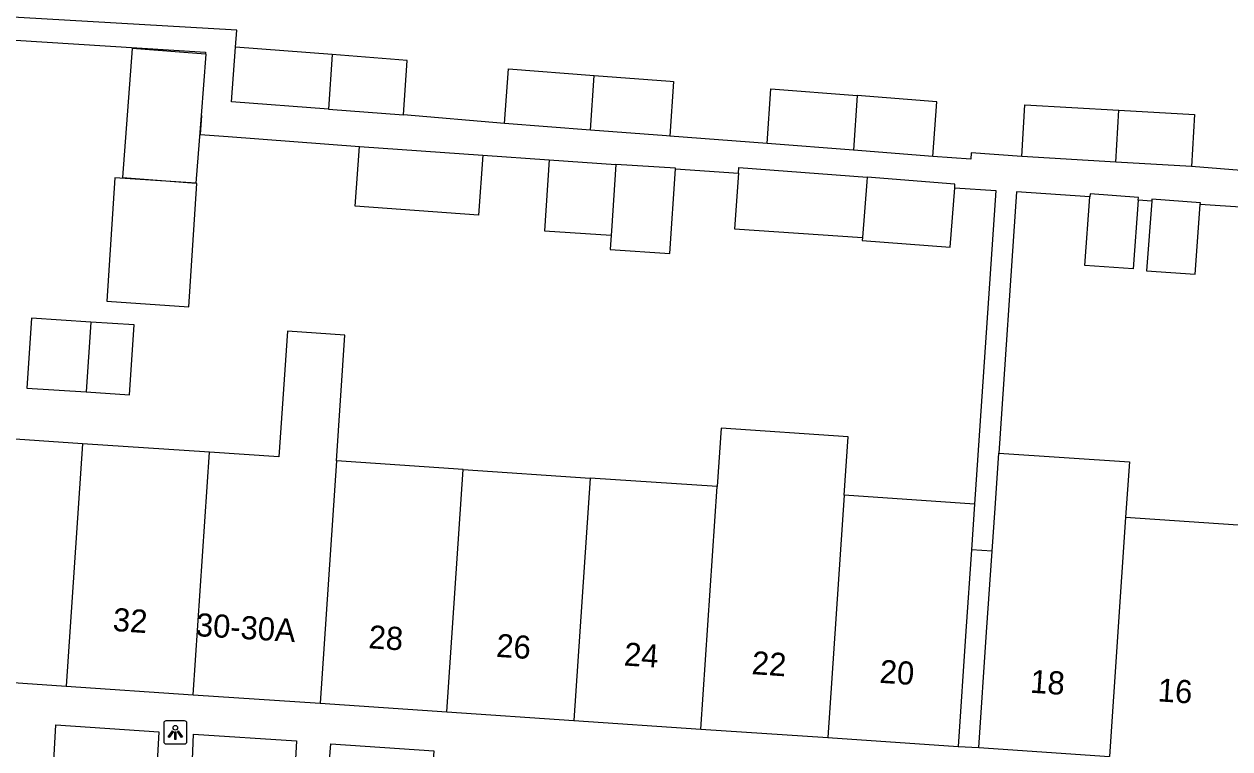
# Model space of a CAD drawing. Extents: x 159961 to 160856, y 382704 to 383353.
# Drawn here: x 160654.9 to 160707.1, y 382890.9 to 382922.3 of the extents above; entities that cross this region are included whole.
import ezdxf

# ---------------------------------------------------------------- set-up
doc = ezdxf.new("R2010")
doc.units = 0
for name, color, linetype in [('IMGEO_Lichtpunt', 7, 'Continuous'), ('IMGEO_Pand', 7, 'Continuous'), ('IMGEO_Pand_nummerreeks', 7, 'Continuous'), ('IMGEO_Pand_overbouw', 7, 'Continuous'), ('IMGEO_Voetpad_open', 7, 'Continuous')]:
    doc.layers.add(name, color=color, linetype=linetype)

msp = doc.modelspace()

# ---------------------------------------------------------------- linework, layer by layer
at = {"layer": 'IMGEO_Lichtpunt'}
for p, q in [((160660.981, 382892.057), (160660.981, 382891.25)), ((160660.981, 382892.057), (160660.981, 382891.25)), ((160661.883, 382892.152), (160661.075, 382892.152)), ((160661.883, 382892.152), (160661.075, 382892.152)), ((160661.977, 382891.25), (160661.977, 382892.057)), ((160661.977, 382891.25), (160661.977, 382892.057)), ((160661.075, 382891.156), (160661.883, 382891.156)), ((160661.075, 382891.156), (160661.883, 382891.156))]:
    msp.add_line(p, q, dxfattribs=at)
for points in [[(160661.355, 382891.721), (160661.394, 382891.693), (160661.206, 382891.431), (160661.168, 382891.458), (160661.355, 382891.721)], [(160661.457, 382891.673), (160661.504, 382891.673), (160661.504, 382891.351), (160661.457, 382891.351), (160661.457, 382891.673)], [(160661.567, 382891.693), (160661.605, 382891.72), (160661.792, 382891.458), (160661.753, 382891.43), (160661.567, 382891.693)]]:
    msp.add_lwpolyline(points, dxfattribs=at)
msp.add_circle((160661.48, 382891.855), 0.0994, dxfattribs=at)
for centre, start, end in [((160661.075, 382892.057), 90, 180), ((160661.075, 382892.057), 90, 180), ((160661.883, 382892.057), 0, 90), ((160661.883, 382892.057), 0, 90), ((160661.075, 382891.25), 180, 270), ((160661.075, 382891.25), 180, 270), ((160661.883, 382891.25), 270, 0), ((160661.883, 382891.25), 270, 360)]:
    msp.add_arc(centre, 0.0946, start, end, dxfattribs=at)
at = {"layer": 'IMGEO_Pand'}
for points in [[(160662.784, 382920.999), (160659.618, 382921.242), (160659.189, 382915.651), (160662.375, 382915.407)], [(160668.102, 382918.612), (160663.905, 382918.935), (160664.086, 382921.294)], [(160668.261, 382920.973), (160664.086, 382921.294)], [(160662.609, 382918.34), (160662.813, 382920.997), (160662.784, 382920.999)], [(160668.261, 382920.973), (160668.102, 382918.612)], [(160671.34, 382918.363), (160671.508, 382920.723), (160668.261, 382920.973)], [(160675.717, 382917.997), (160675.885, 382920.359), (160679.593, 382920.074)], [(160679.431, 382917.712), (160679.593, 382920.074)], [(160679.593, 382920.074), (160682.877, 382919.821), (160683.021, 382919.81), (160682.86, 382917.448)], [(160687.073, 382917.124), (160687.234, 382919.486), (160690.968, 382919.2)], [(160690.968, 382919.2), (160690.806, 382916.837)], [(160694.23, 382916.573), (160694.411, 382918.935), (160690.968, 382919.2)], [(160668.102, 382918.612), (160671.34, 382918.363)], [(160698.086, 382916.56), (160698.215, 382918.8), (160702.28, 382918.566)], [(160662.384, 382915.406), (160662.609, 382918.34)], [(160702.151, 382916.327), (160702.28, 382918.566)], [(160702.28, 382918.566), (160705.546, 382918.378), (160705.417, 382916.139)], [(160679.431, 382917.712), (160675.717, 382917.997)], [(160682.86, 382917.448), (160682.716, 382917.459), (160679.431, 382917.712)], [(160690.806, 382916.837), (160687.073, 382917.124)], [(160674.774, 382916.621), (160674.589, 382914.033), (160669.26, 382914.412), (160669.445, 382917)], [(160669.445, 382917), (160674.774, 382916.621)], [(160694.23, 382916.573), (160690.806, 382916.837)], [(160702.151, 382916.327), (160698.086, 382916.56)], [(160677.637, 382916.418), (160677.435, 382913.347), (160680.328, 382913.157)], [(160677.637, 382916.418), (160680.53, 382916.225)], [(160680.328, 382913.157), (160680.288, 382912.546), (160682.862, 382912.376), (160683.104, 382916.038)], [(160680.53, 382916.225), (160680.341, 382913.349), (160680.328, 382913.157)], [(160683.104, 382916.038), (160683.105, 382916.055), (160680.53, 382916.225)], [(160685.824, 382915.843), (160685.841, 382916.093), (160691.389, 382915.667)], [(160705.417, 382916.139), (160702.151, 382916.327)], [(160662.375, 382915.407), (160658.868, 382915.637), (160658.517, 382910.302), (160662.065, 382910.069), (160662.416, 382915.404), (160662.384, 382915.406)], [(160685.824, 382915.843), (160685.661, 382913.442), (160691.189, 382913.067)], [(160691.389, 382915.667), (160691.374, 382915.468), (160691.189, 382913.067)], [(160695.177, 382915.211), (160695.19, 382915.375), (160691.389, 382915.667)], [(160662.375, 382915.407), (160662.384, 382915.406)], [(160691.189, 382913.067), (160691.179, 382912.932), (160694.98, 382912.64), (160695.177, 382915.211)], [(160703.116, 382914.675), (160703.125, 382914.796), (160701.031, 382914.95), (160701.021, 382914.816)], [(160703.116, 382914.675), (160702.899, 382911.705), (160700.805, 382911.858), (160701.021, 382914.816)], [(160703.698, 382914.635), (160703.478, 382911.623), (160705.572, 382911.47), (160705.794, 382914.494)], [(160705.794, 382914.494), (160705.799, 382914.561), (160703.704, 382914.714), (160703.698, 382914.635)], [(160657.826, 382909.404), (160655.263, 382909.573), (160655.064, 382906.55), (160657.622, 382906.382)], [(160657.826, 382909.404), (160657.622, 382906.382)], [(160657.622, 382906.382), (160659.502, 382906.259), (160659.7, 382909.281), (160657.826, 382909.404)], [(160668.445, 382903.4), (160668.813, 382908.841), (160666.328, 382909.009), (160665.961, 382903.568), (160662.957, 382903.771)], [(160657.47, 382904.142), (160651.833, 382904.524), (160651.461, 382899.027), (160651.124, 382894.038)], [(160690.395, 382901.914), (160690.566, 382904.437), (160685.078, 382904.808), (160684.907, 382902.285)], [(160657.47, 382904.142), (160656.761, 382893.656)], [(160662.957, 382903.771), (160657.47, 382904.142)], [(160662.248, 382893.285), (160662.957, 382903.771)], [(160696.222, 382890.997), (160696.56, 382895.986), (160696.798, 382899.488), (160696.924, 382901.351), (160697.085, 382903.733)], [(160697.085, 382903.733), (160702.731, 382903.351), (160702.57, 382900.969)], [(160668.445, 382903.4), (160667.736, 382892.913)], [(160673.932, 382903.028), (160668.445, 382903.4)], [(160673.223, 382892.542), (160673.932, 382903.028)], [(160673.932, 382903.028), (160679.42, 382902.657)], [(160679.42, 382902.657), (160678.711, 382892.171)], [(160684.907, 382902.285), (160679.42, 382902.657)], [(160684.198, 382891.799), (160684.907, 382902.285)], [(160690.395, 382901.914), (160689.686, 382891.428)], [(160696.034, 382901.532), (160690.395, 382901.914)], [(160696.034, 382901.532), (160695.9, 382899.549), (160695.661, 382896.035), (160695.323, 382891.046)], [(160702.57, 382900.969), (160701.869, 382890.615)], [(160702.57, 382900.969), (160708.069, 382900.596)], [(160651.124, 382894.038), (160656.761, 382893.656)], [(160656.761, 382893.656), (160662.248, 382893.285)], [(160662.248, 382893.285), (160667.736, 382892.913)], [(160667.736, 382892.913), (160673.223, 382892.542)], [(160673.223, 382892.542), (160678.711, 382892.171)], [(160678.711, 382892.171), (160684.198, 382891.799)], [(160684.198, 382891.799), (160689.686, 382891.428)], [(160689.686, 382891.428), (160695.323, 382891.046)], [(160696.222, 382890.997), (160701.869, 382890.615)]]:
    msp.add_lwpolyline(points, dxfattribs=at)
at = {"layer": 'IMGEO_Pand_overbouw'}
msp.add_lwpolyline([(160695.9, 382899.549), (160695.661, 382896.035), (160695.323, 382891.046), (160696.222, 382890.997), (160696.56, 382895.986), (160696.798, 382899.488)], close=True, dxfattribs=at)
at = {"layer": 'IMGEO_Voetpad_open'}
for points in [[(160664.086, 382921.294), (160664.143, 382922.031), (160649.461, 382922.877), (160645.541, 382923.103), (160645.548, 382923.229)], [(160644.513, 382922.238), (160662.789, 382921.078), (160662.784, 382920.999)], [(160662.609, 382918.34), (160662.555, 382917.516), (160663.765, 382917.436), (160669.445, 382917)], [(160675.717, 382917.997), (160671.34, 382918.363)], [(160687.073, 382917.124), (160682.86, 382917.448)], [(160674.774, 382916.621), (160677.637, 382916.418)], [(160698.086, 382916.56), (160695.892, 382916.728), (160695.87, 382916.447), (160694.23, 382916.573)], [(160683.104, 382916.038), (160685.824, 382915.843)], [(160707.92, 382915.934), (160705.417, 382916.139)], [(160695.177, 382915.211), (160696.951, 382915.091), (160696.034, 382901.532)], [(160701.021, 382914.816), (160697.849, 382915.031), (160697.085, 382903.733)], [(160703.698, 382914.635), (160703.116, 382914.675)], [(160741.938, 382911.739), (160741.961, 382912.089), (160705.794, 382914.494)], [(160656.207, 382890.153), (160656.315, 382891.98), (160660.766, 382891.686), (160660.669, 382889.848)], [(160662.19, 382889.744), (160662.264, 382891.576), (160666.722, 382891.292), (160666.619, 382889.441)], [(160668.062, 382889.342), (160668.204, 382891.158), (160672.661, 382890.85), (160672.537, 382889.036)], [(160695.323, 382891.046), (160696.222, 382890.997)]]:
    msp.add_lwpolyline(points, dxfattribs=at)

# ---------------------------------------------------------------- texts
at = {"layer": 'IMGEO_Pand_nummerreeks'}
for s, rotation, p in [('32', 356.1273, (160658.754, 382896.047)), ('30-30A', 356.4935, (160662.346, 382895.821)), ('28', 356.1273, (160669.81, 382895.298)), ('26', 356.1273, (160675.332, 382894.925)), ('24', 356.1273, (160680.857, 382894.551)), ('22', 356.1268, (160686.379, 382894.177)), ('20', 356.1273, (160691.909, 382893.802)), ('18', 356.1252, (160698.421, 382893.374)), ('16', 356.1252, (160703.935, 382893))]:
    msp.add_text(s, height=1, rotation=rotation, dxfattribs=at).set_placement(p)

doc.saveas('drawing.dxf')
